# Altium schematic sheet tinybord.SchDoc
size A4
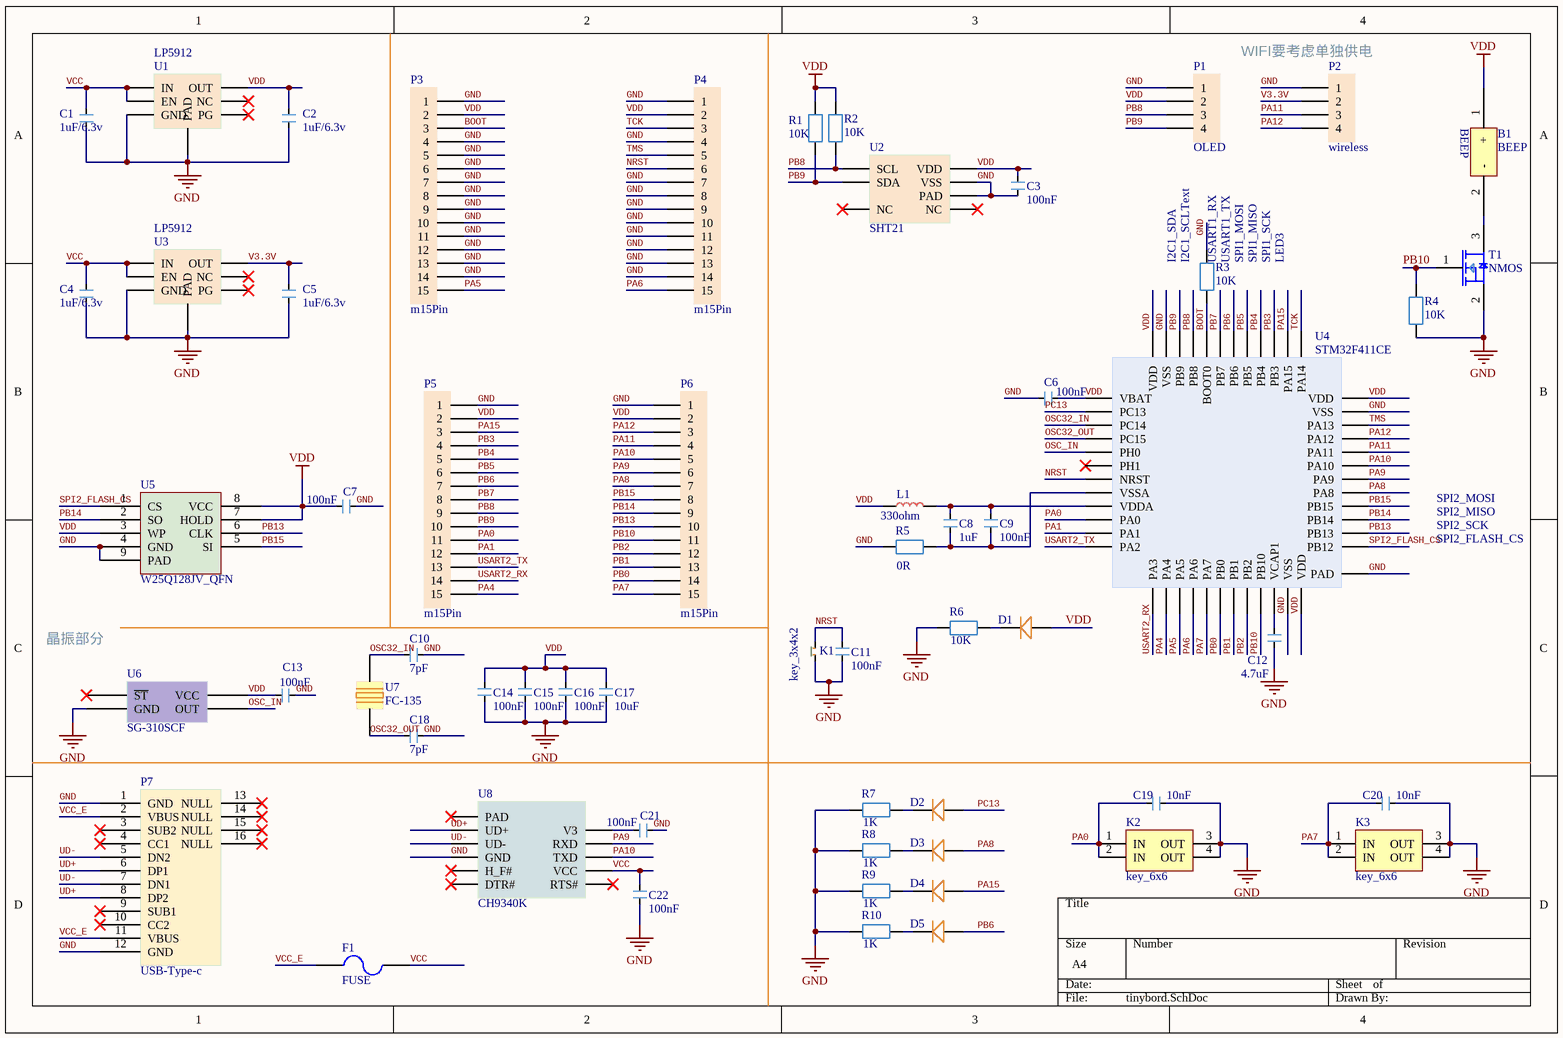
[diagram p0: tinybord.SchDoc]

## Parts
B1  BEEP  [BEEP0905]
C1  value 1uF/6.3v  [C0603]  (hidden comment: C0603)
C2  value 1uF/6.3v  [C0603]  (hidden comment: C0603)
C3  value 100nF  [C0603]  (hidden comment: C0603)
C4  value 1uF/6.3v  [C0603]  (hidden comment: C0603)
C5  value 1uF/6.3v  [C0603]  (hidden comment: C0603)
C6  value 100nF  [C0603]  (hidden comment: C0603)
C7  value 100nF  [C0603]  (hidden comment: C0603)
C8  value 1uF  [C0603]  (hidden comment: C0603)
C9  value 100nF  [C0603]  (hidden comment: C0603)
C10  value 7pF  [C0603]  (hidden comment: C0603)
C11  value 100nF  [C0603]  (hidden comment: C0603)
C12  value 4.7uF  [C0603]  (hidden comment: C0603)
C13  value 100nF  [C0603]  (hidden comment: C0603)
C14  value 100nF  [C0603]  (hidden comment: C0603)
C15  value 100nF  [C0603]  (hidden comment: C0603)
C16  value 100nF  [C0603]  (hidden comment: C0603)
C17  value 10uF  [C0603]  (hidden comment: C0603)
C18  value 7pF  [C0603]  (hidden comment: C0603)
C19  value 10nF  [C0603]  (hidden comment: C0603)
C20  value 10nF  [C0603]  (hidden comment: C0603)
C21  value 100nF  [C0603]  (hidden comment: C0603)
C22  value 100nF  [C0603]  (hidden comment: C0603)
D1  L0603  [led0603]  (value not drawn)
D2  L0603  [led0603]  (value not drawn)
D3  L0603  [led0603]  (value not drawn)
D4  L0603  [led0603]  (value not drawn)
D5  L0603  [led0603]  (value not drawn)
F1  FUSE  [R0603]
K1  key_3x4x2  [Key 3x4x2]
K2  key_6x6  [Key 6x6]
K3  key_6x6  [Key 6x6]
L1  value 330ohm  [B0603]  (hidden comment: B0603)
P1  OLED  [4x1 header]
P2  wireless  [4x1 header]
P3  m15Pin  [15x1 header]
P4  m15Pin  [15x1 header]
P5  m15Pin  [15x1 header]
P6  m15Pin  [15x1 header]
P7  USB-Type-c  [USB-TYPE-C]
R1  value 10K  [R0603]  (hidden comment: R0603)
R2  value 10K  [R0603]  (hidden comment: R0603)
R3  value 10K  [R0603]  (hidden comment: R0603)
R4  value 10K  [R0603]  (hidden comment: R0603)
R5  value 0R  [R0603]  (hidden comment: R0603)
R6  value 10K  [R0603]  (hidden comment: R0603)
R7  value 1K  [R0603]  (hidden comment: R0603)
R8  value 1K  [R0603]  (hidden comment: R0603)
R9  value 1K  [R0603]  (hidden comment: R0603)
R10  value 1K  [R0603]  (hidden comment: R0603)
T1  NMOS  [NMOS-BSH103]
U1  LP5912  [LP5912]
U2  SHT21  [SHT21]
U3  LP5912  [LP5912]
U4  STM32F411CE  [STM32F411CE QFN]
U5  W25Q128JV_QFN  [W25Q64 QFN]
U6  SG-310SCF  [SG-310SCF]
U7  FC-135  [FC-135]
U8  CH9340K  [CH9340]

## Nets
GND: C1.1 C2.1 C3.1 C4.1 C5.1 C6.1 C7.2 C10.1 C11.1 C12.1 C13.2 C14.1 C15.1 C16.1 C17.1 C18.1 C19.1 C20.1 C21.2 C22.1 K1.1 K2.3(OUT) K2.4(OUT) K3.3(OUT) K3.4(OUT) P1.1 P2.1 P3.1 P3.4 P3.5 P3.6 P3.7 P3.8 P3.9 P3.10 P3.11 P3.12 P3.13 P3.14 P4.1 P4.4 P4.7 P4.8 P4.9 P4.10 P4.11 P4.12 P4.13 P4.14 P5.1 P6.1 P7.1(GND) P7.12(GND) R3.2 R4.1 R5.1 R6.1 R7.1 R8.1 R9.1 R10.1 T1.2(S) U1.5(GND) U1.7(PAD) U2.2(VSS) U2.7(PAD) U3.5(GND) U3.7(PAD) U4.23(VSS) U4.35(VSS) U4.47(VSS) U4.49(PAD) U5.4(GND) U5.9(PAD) U6.2(GND) U8.3(GND)
VDD: B1.1(+) C2.2 C3.2 C6.2 C7.1 C13.1 C14.2 C15.2 C16.2 C17.2 D1.2 L1.1 P1.2 P3.2 P4.2 P5.2 P6.2 R1.2 R2.2 U1.1(OUT) U2.5(VDD) U4.1(VBAT) U4.24(VDD) U4.36(VDD) U4.48(VDD) U5.3(WP) U5.7(HOLD) U5.8(VCC) U6.4(VCC)
BOOT: P3.3 R3.1 U4.44(BOOT0)
NRST: C11.2 K1.2 P4.6 U4.7(NRST)
OSC32_IN: C10.2 U4.3(PC14) U7.2
OSC32_OUT: C18.2 U4.4(PC15) U7.1
OSC_IN: U4.5(PH0) U6.3(OUT)
PA0: C19.2 K2.1(IN) K2.2(IN) P5.11 U4.10(PA0)
PA1: P5.12 U4.11(PA1)
PA4: P5.15 U4.14(PA4)
PA5: P3.15 U4.15(PA5)
PA6: P4.15 U4.16(PA6)
PA7: C20.2 K3.1(IN) K3.2(IN) P6.15 U4.17(PA7)
PA8: D3.2 P6.7 U4.29(PA8)
PA9: P6.6 U4.30(PA9) U8.9(RXD)
PA10: P6.5 U4.31(PA10) U8.8(TXD)
PA11: P2.3 P6.4 U4.32(PA11)
PA12: P2.4 P6.3 U4.33(PA12)
PA15: D4.2 P5.3 U4.38(PA15)
PB0: P6.14 U4.18(PB0)
PB1: P6.13 U4.19(PB1)
PB2: P6.12 U4.20(PB2)
PB3: P5.4 U4.39(PB3)
PB4: P5.5 U4.40(PB4)
PB5: P5.6 U4.41(PB5)
PB6: D5.2 P5.7 U4.42(PB6)
PB7: P5.8 U4.43(PB7)
PB8: P1.3 P5.9 R2.1 U2.6(SCL) U4.45(PB8)
PB9: P1.4 P5.10 R1.1 U2.1(SDA) U4.46(PB9)
PB10: P6.11 R4.2 T1.1(G) U4.21(PB10)
PB13: P6.10 U4.26(PB13) U5.6(CLK)
PB14: P6.9 U4.27(PB14) U5.2(SO)
PB15: P6.8 U4.28(PB15) U5.5(SI)
PC13: D2.2 U4.2(PC13)
SPI2_FLASH_CS: U4.25(PB12) U5.1(CS)
TCK: P4.3 U4.37(PA14)
TMS: P4.5 U4.34(PA13)
UD+: P7.6(DP1) P7.8(DP2) U8.1(UD+)
UD-: P7.5(DN2) P7.7(DN1) U8.2(UD-)
USART2_RX: P5.14 U4.13(PA3)
USART2_TX: P5.13 U4.12(PA2)
V3.3V: C5.2 P2.2 U3.1(OUT)
VCC: C1.2 C4.2 C22.2 F1.2 U1.4(EN) U1.6(IN) U3.4(EN) U3.6(IN) U8.7(VCC)
VCC_E: F1.1 P7.2(VBUS) P7.11(VBUS)
NetB1_2: B1.2(-) T1.3(D)
NetC8_1: C8.1 C9.1 R5.2 U4.8(VSSA)
NetC8_2: C8.2 C9.2 L1.2 U4.9(VDDA)
NetC12_2: C12.2 U4.22(VCAP1)
NetC21_1: C21.1 U8.10(V3)
NetD1_1: D1.1 R6.2
NetD2_1: D2.1 R7.2
NetD3_1: D3.1 R8.2
NetD4_1: D4.1 R9.2
NetD5_1: D5.1 R10.2

Not connected (* = marked no-connect by the designer): P7 3(SUB2)* 4(CC1)* 9(SUB1)* 10(CC2)* 13(NULL)* 14(NULL)* 15(NULL)* 16(NULL)*; U1 2(NC)* 3(PG)*; U2 3(NC)* 4(NC)*; U3 2(NC)* 3(PG)*; U4 6(PH1)*; U6 1(~{ST})*; U8 4(H_F#)* 5(DTR#)* 6(RTS#)* 11(PAD)*

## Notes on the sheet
- (near P2) WIFI要考虑单独供电
- (near R3) I2C1_SDA
- (near R3) I2C1_SCLText
- (near R3) USART1_RX
- (near R3) USART1_TX
- (near R3) SPI1_MOSI
- (near R3) SPI1_MISO
- SPI1_SCK
- LED3
- SPI2_MOSI
- SPI2_MISO
- SPI2_SCK
- SPI2_FLASH_CS
- 晶振部分

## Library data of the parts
B1 = BEEP: 12*6
C1-C22 = C0603: 陶瓷电容
D1-D5 = L0603: LED
F1 = PTC0603: PTC 1812
K1 = key_3x4x2: 贴片按键
K2 K3 = key_6x6: 贴片按键
L1 = B0603: 磁珠
P1 P2 = m4Pin: 1x4pin 1.27mm
P3-P6 = m15Pin: 1x4pin 1.27mm
P7 = USB-Type-c: use typec 16p
R1-R10 = R0603: 电阻
T1 = NMOS-BSH103: infineon P-Chanel
U1 U3 = LP5912: LDO
U2 = SHT21: 温湿度传感器
U4 = STM32F411CE: STM32F411 QFN48PIN
U5 = W25Q128JV_QFN: flash
U6 = SG-310SCF: 有源晶振3225
U7 = FC-135: 32.768K无源晶振
U8 = CH9340K: USB转串口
